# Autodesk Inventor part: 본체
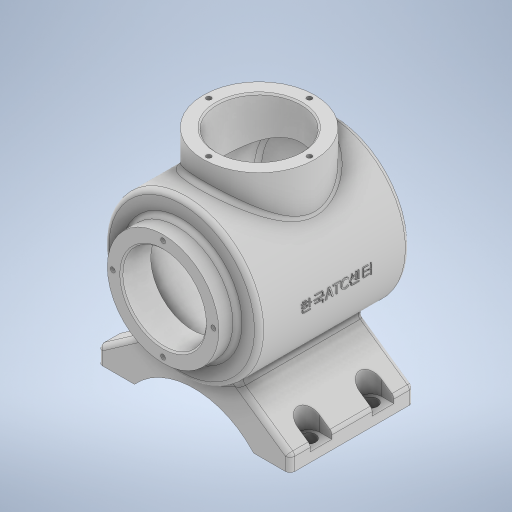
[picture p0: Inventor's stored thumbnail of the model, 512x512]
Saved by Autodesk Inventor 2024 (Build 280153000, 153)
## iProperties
Created: 2023-08
Part Number: 본체
Material: 일반
Document SubType Name: Modeling
Designer: Owner
Density: 1 g/cm^3
Appearance: 기본값
Mass: 474.432 g
Surface Area: 1056.17 cm^2
Volume: 474.432 cm^3
Author: Owner
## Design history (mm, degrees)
sketch "스케치1"
  geometry: L1 (0, 60)-(0, -60); L2 (0, -60)-(0, -8.872); L3 (27, 60)-(36, 60); L4 (36, 60)-(36, 48); L5 (36, 48)-(50, 48); L6 (50, 48)-(50, -48.336); L7 (43, -43.887)-(43, 41); L8 (43, 41)-(27, 41); L9 (27, 41)-(27, 60); A1 r 113 centre (0, 53) between (0, -60) and (50, -48.336); A2 r 106 centre (0, 53) between (0, -53) and (43, -43.887); 2 further points
  constraints: 18 end point, 4 point on circle, 3 perpendicular, 3 vertical, 2 centre point, 2 point on line, 1 coincident, 1 horizontal, 1 horizontal alignment, 1 midpoint, 1 vertical alignment, 1 other
  dimensions: "d1" = 120 distance of L1.start L1.end; "d2" = 113 radius of A1; "d3" = 100 diameter of L6 L1; "d4" = 72 diameter of L4 L1; "d5" = 12 distance of L3.end L4.end; "d6" = 7 radial gap between concentric circles of A1 A2; "d7" = 86 diameter of L7 L1; "d84" = 54 diameter of L9 L1; "d85" = 19 distance of L8.end L3.start (derived)
revolve "회전1" sketch "스케치1" stored, may be unused: angle "d8" = 90 deg
fillet "모깎기1" dims "d9" = 3
node "작업 평면1"
sketch "스케치2"
  geometry: L1 (-36, 60)-(36, 60) reference; C1 r 36 at (0, -2); 1 further point
  constraints: 1 centre point, 1 vertical alignment
  dimensions: "d11" = 72 diameter of C1; "d12" = 62 distance from line of L1 C1.centre
extrude "돌출1" join sketch "스케치2" stored distance "d13" = 10; taper "d14" = 0 deg
sketch "스케치3"
  geometry: L1 (36, -62)-(-36, -62) reference; C1 r 36 at (0, 0) reference; 2 further points
  dimensions: "d15" = 62 distance from line of L1 point (-32.5, 0); "d16" = 32.5 distance of C1.centre point (-32.5, 0)
hole "구멍1" sketch "스케치3" at (-32.5, 0) diameter "d17" = 3.242; stored, may be unused: countersink angle "d21" = 90 deg, drill point angle "d23" = 118 deg; dims "d18" = 8, "d19" = 4, "d20" = 2, "d22" = 10
sketch "스케치4"
  geometry: C1 r 36 at (0, 0) reference; 2 further points
  constraints: 1 coincident
hole "구멍2" sketch "스케치4" at (0, 0) diameter "d24" = 54; stored, may be unused: countersink angle "d28" = 90 deg, drill point angle "d30" = 0 deg; dims "d25" = 8, "d26" = 4, "d27" = 2, "d29" = 10
chamfer "모따기1" distance "d34" = 1; stored, may be unused: second distance "d35" = 2, angle "d36" = 45 deg
fillet "모깎기2" dims "d37" = 3
sketch "스케치5"
  geometry: L1 (-62, -77)-(-62, -67); L2 (62, -77)-(62, -67); L3 (-62, -77)-(-38.5, -77); L4 (62, -77)-(38.5, -77); L5 (-62, -67)-(-26.694, -42.278); L6 (62, -67)-(26.694, -42.278); A1 r 50 centre (0, 0) between (-26.694, -42.278) and (26.694, -42.278) reference; A2 r 52.096 centre (0, -112.096) between (38.5, -77) and (-38.5, -77); 2 further points
  constraints: 12 end point, 5 point on circle, 2 equal length, 2 horizontal, 2 vertical, 1 centre point, 1 vertical alignment
  dimensions: "d38" = 17 vertical distance of L4.end point (0, -60); "d39" = 77 vertical distance of L2.start point (0, 0); "d40" = 77 vertical distance of L1.start point (0, 0); "d41" = 77 distance of L4.end L3.end; "d43" = 10 distance of L2.start L2.end; "d45" = 124 distance of L2.end L1.end; "d46" = 55 deg angle of L1 L5; "d47" = 55 deg angle of L2 L6
extrude "돌출2" join sketch "스케치5" stored distance "d48" = 80; taper "d49" = 0 deg
node "작업 평면2"
sketch "스케치6"
  geometry: L1 (23.5, -80)-(0, -80) reference; L2 (23.5, -80)-(23.5, 0) reference; L3 (15.5, -67)-(23.5, -67); L4 (15.5, -53)-(23.5, -53); A1 r 7 centre (15.5, -60) between (15.5, -67) and (15.5, -53); 1 further point
  constraints: 4 end point, 2 perpendicular, 2 point on circle, 2 point on line, 2 tangent, 1 centre point
  dimensions: "d51" = 14 diameter of A1; "d52" = 20 distance from line of L1 A1.centre; "d53" = 8 distance from line of L2 A1.centre
extrude "돌출3" cut sketch "스케치6" distance "d54" = 50; taper "d55" = 0 deg
sketch "스케치7"
  geometry: A1 r 7 centre (15.5, 60) between (15.5, 67) and (15.5, 53) reference; 2 further points
  constraints: 1 coincident
hole "구멍3" sketch "스케치7" at (15.5, 60) diameter "d56" = 9; stored, may be unused: countersink angle "d60" = 90 deg, drill point angle "d62" = 0 deg; dims "d57" = 6, "d58" = 4, "d59" = 2, "d61" = 8
sketch "스케치8"
  geometry: 2 further points
  constraints: 1 vertical alignment
  dimensions: "d66" = 32.5 distance of point (0, 0) point (0, 32.5)
hole "구멍4" sketch "스케치8" at (0, 32.5) diameter "d67" = 3.242; stored, may be unused: countersink angle "d71" = 90 deg, drill point angle "d73" = 118 deg; dims "d68" = 8, "d69" = 4, "d70" = 2, "d72" = 10
fillet "모깎기3" dims "d74" = 3
fillet "모깎기4" dims "d75" = 3
fillet "모깎기5" dims "d76" = 3
node "작업 평면3"
sketch "스케치9"
  geometry: L1 (-36, 60.168)-(36, 60.168) reference; 3 further points
  constraints: 1 midpoint, 1 vertical alignment, 1 other
  dimensions: "d81" = 62 distance from line of L1 point (0, -1.832)
feature "엠보싱1" sketch "스케치9" dims "d1" = 120, "d2" = 113, "d3" = 100, "d4" = 72, "d5" = 12, "d6" = 7, "d7" = 86, "d11" = 72, "d12" = 62, "d82" = 0.5, "d83" = 0, "d84" = 54, "d85" = 19 (derived)
feature "ʵ耀ʷ耀ʹ耀ʻ耀ʽ耀ʿ耀ˁ耀˃耀" dims "d1" = 120, "d2" = 113, "d3" = 100, "d4" = 72, "d5" = 12, "d6" = 7, "d7" = 86, "d8" = 90 deg, "d9" = 3, "d10" = 65, "d11" = 72, "d12" = 62, "d13" = 10, "d14" = 0, "d15" = 62, "d16" = 32.5, "d17" = 3.242, "d18" = 8, "d19" = 4, "d20" = 2, "d21" = 90 deg, "d22" = 10, "d23" = 118 deg, "d24" = 54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
node "솔리드1"
pattern_circular "원형 패턴1" dims angle "d32" = 360 deg
pattern_linear "직사각형 패턴1" dims "d65" = 40
mirror "미러1"
pattern_circular "원형 패턴2" dims angle "d78" = 360 deg
feature "A9D066F2-1C7D-4E18-AEED-F7BC21143FA4" dims "d56" = 9, "d57" = 6, "d58" = 4, "d59" = 2, "d60" = 90 deg, "d61" = 8, "d62" = 0
